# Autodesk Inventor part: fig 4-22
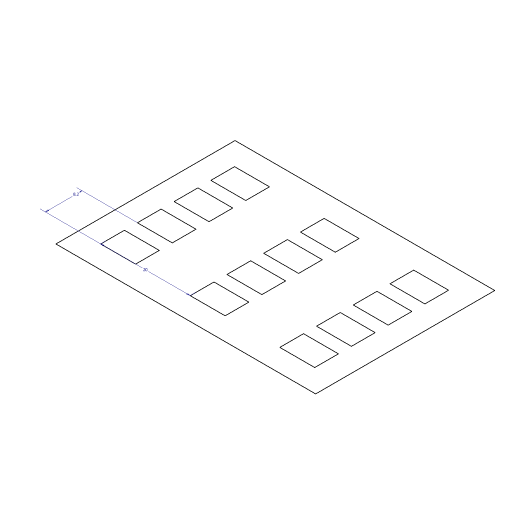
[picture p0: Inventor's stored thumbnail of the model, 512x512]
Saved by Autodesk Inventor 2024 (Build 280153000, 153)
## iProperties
Created: 2004-05
Part Number: fig 4-22
Document SubType Name: Modeling
Designer: CADCIM Technologies
Manufacturer: Standard
Standards Organization: Custom
Density: 1 g/cm^3
Material: Generic
Appearance: Default
Author: CADCIM Technologies
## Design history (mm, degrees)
sketch "Sketch1"
  geometry: L1 (7.752, 6.176)-(65.752, 6.176); L2 (65.752, 6.176)-(65.752, 46.176); L3 (65.752, 46.176)-(7.752, 46.176); L4 (7.752, 46.176)-(7.752, 6.176); L5 (12.752, 11.176)-(20.543, 11.176); L6 (20.543, 11.176)-(20.543, 16.473); L7 (20.543, 16.473)-(12.752, 16.473); L8 (12.752, 16.473)-(12.752, 11.176); L9 (32.752, 11.176)-(40.543, 11.176); L10 (40.543, 11.176)-(40.543, 16.473); L11 (40.543, 16.473)-(32.752, 16.473); L12 (32.752, 16.473)-(32.752, 11.176); L13 (52.752, 11.176)-(60.543, 11.176); L14 (60.543, 11.176)-(60.543, 16.473); L15 (60.543, 16.473)-(52.752, 16.473); L16 (52.752, 16.473)-(52.752, 11.176); L17 (12.752, 19.376)-(20.543, 19.376); L18 (20.543, 19.376)-(20.543, 24.673); L19 (20.543, 24.673)-(12.752, 24.673); L20 (12.752, 24.673)-(12.752, 19.376); L21 (32.752, 19.376)-(40.543, 19.376); L22 (40.543, 19.376)-(40.543, 24.673); L23 (40.543, 24.673)-(32.752, 24.673); L24 (32.752, 24.673)-(32.752, 19.376); L25 (52.752, 19.376)-(60.543, 19.376); L26 (60.543, 19.376)-(60.543, 24.673); L27 (60.543, 24.673)-(52.752, 24.673); L28 (52.752, 24.673)-(52.752, 19.376); L29 (12.752, 27.576)-(20.543, 27.576); L30 (20.543, 27.576)-(20.543, 32.873); L31 (20.543, 32.873)-(12.752, 32.873); L32 (12.752, 32.873)-(12.752, 27.576); L33 (32.752, 27.576)-(40.543, 27.576); L34 (40.543, 27.576)-(40.543, 32.873); L35 (40.543, 32.873)-(32.752, 32.873); L36 (32.752, 32.873)-(32.752, 27.576); L37 (52.752, 27.576)-(60.543, 27.576); L38 (60.543, 27.576)-(60.543, 32.873); L39 (60.543, 32.873)-(52.752, 32.873); L40 (52.752, 32.873)-(52.752, 27.576); L41 (12.752, 35.776)-(20.543, 35.776); L42 (20.543, 35.776)-(20.543, 41.073); L43 (20.543, 41.073)-(12.752, 41.073); L44 (12.752, 41.073)-(12.752, 35.776); L45 (32.752, 35.776)-(40.543, 35.776); L46 (40.543, 35.776)-(40.543, 41.073); L47 (40.543, 41.073)-(32.752, 41.073); L48 (32.752, 41.073)-(32.752, 35.776); L49 (52.752, 35.776)-(60.543, 35.776); L50 (60.543, 35.776)-(60.543, 41.073); L51 (60.543, 41.073)-(52.752, 41.073); L52 (52.752, 41.073)-(52.752, 35.776)
  constraints: 104 end point, 4 parallel, 3 horizontal, 2 perpendicular, 1 vertical, 88 other
  dimensions: "d14" = 20 distance of L5.start L9.start; "d17" = 8.2 distance of L5.start L17.start
